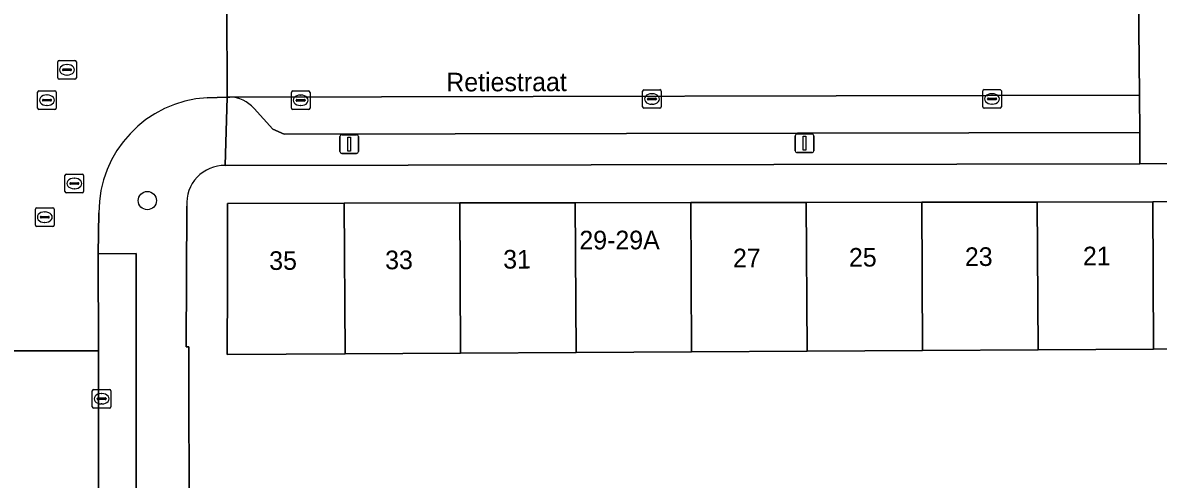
# Model space of a CAD drawing. Extents: x 160732 to 162107, y 387428 to 388479.
# Drawn here: x 161157.5 to 161218.5, y 387935.7 to 387960.1 of the extents above; entities that cross this region are included whole.
import ezdxf

# ---------------------------------------------------------------- set-up
doc = ezdxf.new("R2010")
doc.units = 0
for name, color, linetype in [('IMGEO_Boom', 7, 'Continuous'), ('IMGEO_Erf', 7, 'Continuous'), ('IMGEO_Kolk', 7, 'Continuous'), ('IMGEO_Lichtmast', 7, 'Continuous'), ('IMGEO_Openbare_ruimte_label', 7, 'Continuous'), ('IMGEO_Pand', 7, 'Continuous'), ('IMGEO_Pand_nummerreeks', 7, 'Continuous'), ('IMGEO_Parkeervlak_open', 7, 'Continuous'), ('IMGEO_Rijbaan_lokaal_open', 7, 'Continuous'), ('IMGEO_Rioolput', 7, 'Continuous'), ('IMGEO_Voetpad_open', 7, 'Continuous')]:
    doc.layers.add(name, color=color, linetype=linetype)

msp = doc.modelspace()

# ---------------------------------------------------------------- linework, layer by layer
at = {"layer": 'IMGEO_Boom'}
msp.add_circle((161164.237, 387950.611), 0.489, dxfattribs=at)
at = {"layer": 'IMGEO_Erf'}
for points in [[(161243.083, 387952.638), (161217.507, 387952.589), (161168.418, 387952.495)], [(161166.352, 387950.318), (161166.323, 387942.76), (161166.474, 387942.759), (161166.481, 387932.401)], [(161224.443, 387942.674), (161218.243, 387942.639), (161212.044, 387942.605), (161205.845, 387942.57), (161199.646, 387942.535), (161193.447, 387942.501), (161187.247, 387942.466), (161181.048, 387942.431), (161174.849, 387942.396), (161168.521, 387942.361), (161168.535, 387946.227), (161168.535, 387950.459), (161174.808, 387950.47), (161181.005, 387950.481), (161187.204, 387950.491), (161193.403, 387950.502), (161199.602, 387950.513), (161205.801, 387950.523), (161212, 387950.534), (161218.199, 387950.545), (161224.399, 387950.555)]]:
    msp.add_lwpolyline(points, dxfattribs=at)
msp.add_arc((161168.389, 387950.454), 2.041, 89.17868, 183.81844, dxfattribs=at)
at = {"layer": 'IMGEO_Kolk'}
for p, q in [((161171.967, 387955.563), (161171.967, 387956.415)), ((161172.042, 387956.489), (161172.894, 387956.489)), ((161172.968, 387956.415), (161172.968, 387955.563)), ((161190.816, 387955.632), (161190.816, 387956.484)), ((161190.891, 387956.558), (161191.743, 387956.558)), ((161191.304, 387956.338), (161191.329, 387956.338)), ((161191.817, 387956.484), (161191.817, 387955.632)), ((161209.072, 387955.635), (161209.072, 387956.487)), ((161209.147, 387956.561), (161209.999, 387956.561)), ((161209.56, 387956.341), (161209.585, 387956.341)), ((161210.073, 387956.487), (161210.073, 387955.635)), ((161172.226, 387955.983), (161172.226, 387955.995)), ((161172.664, 387955.946), (161172.266, 387955.946)), ((161172.269, 387956.032), (161172.667, 387956.032)), ((161172.478, 387955.709), (161172.453, 387955.709)), ((161172.455, 387956.269), (161172.48, 387956.269)), ((161172.71, 387955.995), (161172.71, 387955.983)), ((161191.075, 387956.052), (161191.075, 387956.064)), ((161191.513, 387956.015), (161191.115, 387956.015)), ((161191.118, 387956.101), (161191.516, 387956.101)), ((161191.327, 387955.778), (161191.302, 387955.778)), ((161191.559, 387956.064), (161191.559, 387956.052)), ((161209.331, 387956.055), (161209.331, 387956.067)), ((161209.769, 387956.018), (161209.371, 387956.018)), ((161209.374, 387956.104), (161209.772, 387956.104)), ((161209.583, 387955.781), (161209.558, 387955.781)), ((161209.815, 387956.067), (161209.815, 387956.055)), ((161172.894, 387955.489), (161172.042, 387955.489)), ((161191.743, 387955.558), (161190.891, 387955.558)), ((161209.999, 387955.561), (161209.147, 387955.561)), ((161161.358, 387940.483), (161162.21, 387940.483)), ((161161.283, 387939.557), (161161.283, 387940.409)), ((161161.542, 387939.977), (161161.542, 387939.989)), ((161161.98, 387939.94), (161161.582, 387939.94)), ((161161.585, 387940.026), (161161.983, 387940.026)), ((161161.771, 387940.263), (161161.796, 387940.263)), ((161162.026, 387939.989), (161162.026, 387939.977)), ((161162.284, 387940.409), (161162.284, 387939.557)), ((161162.21, 387939.483), (161161.358, 387939.483)), ((161161.794, 387939.703), (161161.769, 387939.703))]:
    msp.add_line(p, q, dxfattribs=at)
for points in [[(161171.967, 387955.563), (161171.967, 387956.415)], [(161172.042, 387956.489), (161172.894, 387956.489)], [(161172.968, 387956.415), (161172.968, 387955.563)], [(161190.816, 387955.632), (161190.816, 387956.484)], [(161190.891, 387956.558), (161191.743, 387956.558)], [(161191.817, 387956.484), (161191.817, 387955.632)], [(161209.072, 387955.635), (161209.072, 387956.487)], [(161209.147, 387956.561), (161209.999, 387956.561)], [(161210.073, 387956.487), (161210.073, 387955.635)], [(161172.894, 387955.489), (161172.042, 387955.489)], [(161191.743, 387955.558), (161190.891, 387955.558)], [(161209.999, 387955.561), (161209.147, 387955.561)], [(161161.358, 387940.483), (161162.21, 387940.483)], [(161161.283, 387939.557), (161161.283, 387940.409)], [(161162.284, 387940.409), (161162.284, 387939.557)], [(161162.21, 387939.483), (161161.358, 387939.483)]]:
    msp.add_lwpolyline(points, dxfattribs=at)
for centre, radius, start, end in [((161172.044, 387956.413), 0.0765, 91.55205, 178.44795), ((161172.044, 387956.413), 0.0765, 91.55205, 178.44795), ((161172.892, 387956.413), 0.0765, 1.55205, 88.44795), ((161172.892, 387956.413), 0.0765, 1.55205, 88.44795), ((161190.893, 387956.482), 0.0765, 91.55205, 178.44795), ((161190.893, 387956.482), 0.0765, 91.55205, 178.44795), ((161191.741, 387956.482), 0.0765, 1.55205, 88.44795), ((161191.741, 387956.482), 0.0765, 1.55205, 88.44795), ((161209.149, 387956.485), 0.0765, 91.55205, 178.44795), ((161209.149, 387956.485), 0.0765, 91.55205, 178.44795), ((161209.997, 387956.485), 0.0765, 1.55205, 88.44795), ((161209.997, 387956.485), 0.0765, 1.55205, 88.44795), ((161172.266, 387955.992), 0.0403, 85.87752, 175.75265), ((161172.263, 387955.982), 0.0366, 178.93798, 274.71019), ((161172.667, 387955.989), 0.043, 264.86636, 352.45326), ((161172.671, 387955.994), 0.0386, 1.73085, 96.63898), ((161191.115, 387956.061), 0.0403, 85.87752, 175.75265), ((161191.112, 387956.051), 0.0366, 178.93798, 274.71019), ((161191.516, 387956.058), 0.043, 264.86636, 352.45326), ((161191.52, 387956.063), 0.0386, 1.73085, 96.63898), ((161209.371, 387956.064), 0.0403, 85.87752, 175.75265), ((161209.368, 387956.054), 0.0366, 178.93798, 274.71019), ((161209.772, 387956.061), 0.043, 264.86636, 352.45326), ((161209.776, 387956.066), 0.0386, 1.73085, 96.63898), ((161172.044, 387955.565), 0.0765, 181.55205, 268.44795), ((161172.044, 387955.565), 0.0765, 181.55205, 268.44795), ((161172.892, 387955.565), 0.0765, 271.55205, 358.44795), ((161172.892, 387955.565), 0.0765, 271.55205, 358.44795), ((161190.893, 387955.634), 0.0765, 181.55205, 268.44795), ((161190.893, 387955.634), 0.0765, 181.55205, 268.44795), ((161191.741, 387955.634), 0.0765, 271.55205, 358.44795), ((161191.741, 387955.634), 0.0765, 271.55205, 358.44795), ((161209.149, 387955.637), 0.0765, 181.55205, 268.44795), ((161209.149, 387955.637), 0.0765, 181.55205, 268.44795), ((161209.997, 387955.637), 0.0765, 271.55205, 358.44795), ((161209.997, 387955.637), 0.0765, 271.55205, 358.44795), ((161161.36, 387940.407), 0.0765, 91.55205, 178.44795), ((161161.36, 387940.407), 0.0765, 91.55205, 178.44795), ((161162.208, 387940.407), 0.0765, 1.55205, 88.44795), ((161162.208, 387940.407), 0.0765, 1.55205, 88.44795), ((161161.582, 387939.986), 0.0403, 85.87752, 175.75265), ((161161.579, 387939.976), 0.0366, 178.93798, 274.71019), ((161161.983, 387939.983), 0.043, 264.86636, 352.45326), ((161161.987, 387939.988), 0.0386, 1.73085, 96.63898), ((161161.36, 387939.559), 0.0765, 181.55205, 268.44795), ((161161.36, 387939.559), 0.0765, 181.55205, 268.44795), ((161162.208, 387939.559), 0.0765, 271.55205, 358.44795), ((161162.208, 387939.559), 0.0765, 271.55205, 358.44795)]:
    msp.add_arc(centre, radius, start, end, dxfattribs=at)
for centre, major_axis, ratio, start_param, end_param in [((161191.303, 387956.058), (-0.387, 0.002), 0.722429, 4.712389, 7.853982), ((161191.328, 387956.058), (-0.39, 0.002), 0.717154, 1.570796, 4.712389), ((161209.559, 387956.061), (-0.387, 0.002), 0.722429, 4.712389, 7.853982), ((161209.584, 387956.061), (-0.39, 0.002), 0.717154, 1.570796, 4.712389), ((161172.454, 387955.989), (-0.387, 0.002), 0.722429, 4.712389, 7.853982), ((161172.479, 387955.989), (-0.39, 0.002), 0.717154, 1.570796, 4.712389), ((161161.77, 387939.983), (-0.387, 0.002), 0.722429, 4.712389, 7.853982), ((161161.795, 387939.983), (-0.39, 0.002), 0.717154, 1.570796, 4.712389)]:
    msp.add_ellipse(centre, major_axis=major_axis, ratio=ratio, start_param=start_param, end_param=end_param, dxfattribs=at)
at = {"layer": 'IMGEO_Lichtmast'}
for p, q in [((161174.573, 387953.242), (161174.573, 387954.042)), ((161174.573, 387954.042), (161174.573, 387953.242)), ((161174.673, 387954.142), (161175.463, 387954.142)), ((161175.463, 387954.142), (161174.673, 387954.142)), ((161175.563, 387954.042), (161175.563, 387953.242)), ((161175.563, 387953.242), (161175.563, 387954.042)), ((161199.013, 387953.282), (161199.013, 387954.082)), ((161199.013, 387954.082), (161199.013, 387953.282)), ((161199.113, 387954.182), (161199.903, 387954.182)), ((161199.903, 387954.182), (161199.113, 387954.182)), ((161200.003, 387954.082), (161200.003, 387953.282)), ((161200.003, 387953.282), (161200.003, 387954.082)), ((161175.463, 387953.142), (161174.673, 387953.142)), ((161174.673, 387953.142), (161175.463, 387953.142)), ((161199.903, 387953.182), (161199.113, 387953.182)), ((161199.113, 387953.182), (161199.903, 387953.182))]:
    msp.add_line(p, q, dxfattribs=at)
for points in [[(161174.993, 387954.017), (161175.143, 387954.017), (161175.143, 387953.267), (161174.993, 387953.267), (161174.993, 387954.017)], [(161199.433, 387954.057), (161199.583, 387954.057), (161199.583, 387953.307), (161199.433, 387953.307), (161199.433, 387954.057)]]:
    msp.add_lwpolyline(points, dxfattribs=at)
for centre, start, end in [((161174.673, 387954.042), 90, 180), ((161174.673, 387954.042), 90, 180), ((161175.463, 387954.042), 0, 90), ((161175.463, 387954.042), 360, 90), ((161199.113, 387954.082), 90, 180), ((161199.113, 387954.082), 90, 180), ((161199.903, 387954.082), 0, 90), ((161199.903, 387954.082), 360, 90), ((161199.113, 387953.282), 180, 270), ((161199.113, 387953.282), 180, 270), ((161199.903, 387953.282), 270, 0), ((161199.903, 387953.282), 270, 0), ((161174.673, 387953.242), 180, 270), ((161174.673, 387953.242), 180, 270), ((161175.463, 387953.242), 270, 0), ((161175.463, 387953.242), 270, 0)]:
    msp.add_arc(centre, 0.1, start, end, dxfattribs=at)
at = {"layer": 'IMGEO_Pand'}
for points in [[(161168.535, 387950.459), (161168.535, 387946.227), (161168.521, 387942.361), (161174.849, 387942.396), (161174.808, 387950.47)], [(161174.808, 387950.47), (161174.849, 387942.396), (161181.048, 387942.431), (161181.005, 387950.481)], [(161181.005, 387950.481), (161181.048, 387942.431), (161187.247, 387942.466), (161187.204, 387950.491)], [(161193.403, 387950.502), (161187.204, 387950.491), (161187.247, 387942.466), (161193.447, 387942.501)], [(161193.403, 387950.502), (161193.447, 387942.501), (161199.646, 387942.535), (161199.602, 387950.513)], [(161199.602, 387950.513), (161199.646, 387942.535), (161205.845, 387942.57), (161205.801, 387950.523)], [(161205.801, 387950.523), (161205.845, 387942.57), (161212.044, 387942.605), (161212, 387950.534)], [(161212, 387950.534), (161212.044, 387942.605), (161218.243, 387942.639), (161218.199, 387950.545)], [(161218.199, 387950.545), (161218.243, 387942.639), (161224.443, 387942.674), (161224.399, 387950.555)]]:
    msp.add_lwpolyline(points, close=True, dxfattribs=at)
at = {"layer": 'IMGEO_Parkeervlak_open'}
for points in [[(161169.968, 387955.554), (161170.974, 387954.445), (161171.575, 387954.168), (161217.496, 387954.255), (161217.48, 387956.261), (161168.663, 387956.165)], [(161163.64, 387917.113), (161163.631, 387947.771), (161161.599, 387947.756), (161161.618, 387942.56), (161161.627, 387913.997)]]:
    msp.add_lwpolyline(points, dxfattribs=at)
msp.add_arc((161168.595, 387954.321), 1.845, 41.92361, 87.89847, dxfattribs=at)
at = {"layer": 'IMGEO_Rijbaan_lokaal_open'}
msp.add_lwpolyline([(161173.705, 387961.122), (161168.507, 387961.118), (161168.516, 387956.165), (161168.663, 387956.165), (161217.48, 387956.261), (161217.376, 387967.03), (161212.367, 387967.026), (161212.393, 387961.222)], close=True, dxfattribs=at)
for points in [[(161167.441, 387956.125), (161168.516, 387956.165), (161168.507, 387961.118), (161166.739, 387961.141)], [(161156.678, 387943.627), (161156.704, 387942.547), (161161.618, 387942.56), (161161.599, 387947.756), (161161.64, 387949.955)], [(161161.627, 387913.926), (161161.627, 387913.997), (161161.618, 387942.56), (161156.704, 387942.547), (161156.776, 387906.254), (161156.817, 387879.896), (161156.803, 387874.965), (161156.836, 387859.504), (161161.733, 387859.513), (161161.702, 387896.422)]]:
    msp.add_lwpolyline(points, dxfattribs=at)
msp.add_arc((161167.792, 387949.983), 6.152, 93.2734, 180.2577, dxfattribs=at)
at = {"layer": 'IMGEO_Rioolput'}
for p, q in [((161159.427, 387957.198), (161159.427, 387958.05)), ((161159.502, 387958.124), (161160.354, 387958.124)), ((161159.686, 387957.618), (161159.686, 387957.63)), ((161160.124, 387957.581), (161159.726, 387957.581)), ((161159.729, 387957.667), (161160.127, 387957.667)), ((161159.915, 387957.904), (161159.94, 387957.904)), ((161160.17, 387957.63), (161160.17, 387957.618)), ((161160.428, 387958.05), (161160.428, 387957.198)), ((161160.354, 387957.124), (161159.502, 387957.124)), ((161159.938, 387957.344), (161159.913, 387957.344)), ((161158.349, 387955.568), (161158.349, 387956.42)), ((161158.424, 387956.494), (161159.276, 387956.494)), ((161159.35, 387956.42), (161159.35, 387955.568)), ((161158.608, 387955.988), (161158.608, 387956)), ((161159.046, 387955.951), (161158.648, 387955.951)), ((161158.651, 387956.037), (161159.049, 387956.037)), ((161158.86, 387955.714), (161158.835, 387955.714)), ((161158.837, 387956.274), (161158.862, 387956.274)), ((161159.092, 387956), (161159.092, 387955.988)), ((161159.276, 387955.494), (161158.424, 387955.494)), ((161159.817, 387951.101), (161159.817, 387951.953)), ((161159.892, 387952.027), (161160.744, 387952.027)), ((161160.076, 387951.521), (161160.076, 387951.533)), ((161160.514, 387951.484), (161160.116, 387951.484)), ((161160.119, 387951.57), (161160.517, 387951.57)), ((161160.305, 387951.807), (161160.33, 387951.807)), ((161160.56, 387951.533), (161160.56, 387951.521)), ((161160.818, 387951.953), (161160.818, 387951.101)), ((161160.744, 387951.027), (161159.892, 387951.027)), ((161160.328, 387951.247), (161160.303, 387951.247)), ((161158.31, 387950.221), (161159.162, 387950.221)), ((161158.235, 387949.295), (161158.235, 387950.147)), ((161158.494, 387949.715), (161158.494, 387949.727)), ((161158.932, 387949.678), (161158.534, 387949.678)), ((161158.537, 387949.764), (161158.935, 387949.764)), ((161158.723, 387950.001), (161158.748, 387950.001)), ((161158.978, 387949.727), (161158.978, 387949.715)), ((161159.236, 387950.147), (161159.236, 387949.295)), ((161159.162, 387949.221), (161158.31, 387949.221)), ((161158.746, 387949.441), (161158.721, 387949.441))]:
    msp.add_line(p, q, dxfattribs=at)
for points in [[(161159.427, 387957.198), (161159.427, 387958.05)], [(161159.502, 387958.124), (161160.354, 387958.124)], [(161160.428, 387958.05), (161160.428, 387957.198)], [(161160.354, 387957.124), (161159.502, 387957.124)], [(161158.349, 387955.568), (161158.349, 387956.42)], [(161158.424, 387956.494), (161159.276, 387956.494)], [(161159.35, 387956.42), (161159.35, 387955.568)], [(161159.276, 387955.494), (161158.424, 387955.494)], [(161159.817, 387951.101), (161159.817, 387951.953)], [(161159.892, 387952.027), (161160.744, 387952.027)], [(161160.818, 387951.953), (161160.818, 387951.101)], [(161160.744, 387951.027), (161159.892, 387951.027)], [(161158.31, 387950.221), (161159.162, 387950.221)], [(161158.235, 387949.295), (161158.235, 387950.147)], [(161159.236, 387950.147), (161159.236, 387949.295)], [(161159.162, 387949.221), (161158.31, 387949.221)]]:
    msp.add_lwpolyline(points, dxfattribs=at)
for centre, radius, start, end in [((161159.504, 387958.048), 0.0765, 91.55205, 178.44795), ((161159.504, 387958.048), 0.0765, 91.55205, 178.44795), ((161159.726, 387957.627), 0.0403, 85.87752, 175.75265), ((161159.723, 387957.617), 0.0366, 178.93798, 274.71019), ((161160.127, 387957.624), 0.043, 264.86636, 352.45326), ((161160.131, 387957.629), 0.0386, 1.73085, 96.63898), ((161160.352, 387958.048), 0.0765, 1.55205, 88.44795), ((161160.352, 387958.048), 0.0765, 1.55205, 88.44795), ((161159.504, 387957.2), 0.0765, 181.55205, 268.44795), ((161159.504, 387957.2), 0.0765, 181.55205, 268.44795), ((161160.352, 387957.2), 0.0765, 271.55205, 358.44795), ((161160.352, 387957.2), 0.0765, 271.55205, 358.44795), ((161158.426, 387956.418), 0.0765, 91.55205, 178.44795), ((161158.426, 387956.418), 0.0765, 91.55205, 178.44795), ((161159.274, 387956.418), 0.0765, 1.55205, 88.44795), ((161159.274, 387956.418), 0.0765, 1.55205, 88.44795), ((161158.648, 387955.997), 0.0403, 85.87752, 175.75265), ((161158.645, 387955.987), 0.0366, 178.93798, 274.71019), ((161159.049, 387955.994), 0.043, 264.86636, 352.45326), ((161159.053, 387955.999), 0.0386, 1.73085, 96.63898), ((161158.426, 387955.57), 0.0765, 181.55205, 268.44795), ((161158.426, 387955.57), 0.0765, 181.55205, 268.44795), ((161159.274, 387955.57), 0.0765, 271.55205, 358.44795), ((161159.274, 387955.57), 0.0765, 271.55205, 358.44795), ((161159.894, 387951.951), 0.0765, 91.55205, 178.44795), ((161159.894, 387951.951), 0.0765, 91.55205, 178.44795), ((161160.116, 387951.53), 0.0403, 85.87752, 175.75265), ((161160.113, 387951.52), 0.0366, 178.93798, 274.71019), ((161160.517, 387951.527), 0.043, 264.86636, 352.45326), ((161160.521, 387951.532), 0.0386, 1.73085, 96.63898), ((161160.742, 387951.951), 0.0765, 1.55205, 88.44795), ((161160.742, 387951.951), 0.0765, 1.55205, 88.44795), ((161159.894, 387951.103), 0.0765, 181.55205, 268.44795), ((161159.894, 387951.103), 0.0765, 181.55205, 268.44795), ((161160.742, 387951.103), 0.0765, 271.55205, 358.44795), ((161160.742, 387951.103), 0.0765, 271.55205, 358.44795), ((161158.312, 387950.145), 0.0765, 91.55205, 178.44795), ((161158.312, 387950.145), 0.0765, 91.55205, 178.44795), ((161159.16, 387950.145), 0.0765, 1.55205, 88.44795), ((161159.16, 387950.145), 0.0765, 1.55205, 88.44795), ((161158.534, 387949.724), 0.0403, 85.87752, 175.75265), ((161158.531, 387949.714), 0.0366, 178.93798, 274.71019), ((161158.935, 387949.721), 0.043, 264.86636, 352.45326), ((161158.939, 387949.726), 0.0386, 1.73085, 96.63898), ((161158.312, 387949.297), 0.0765, 181.55205, 268.44795), ((161158.312, 387949.297), 0.0765, 181.55205, 268.44795), ((161159.16, 387949.297), 0.0765, 271.55205, 358.44795), ((161159.16, 387949.297), 0.0765, 271.55205, 358.44795)]:
    msp.add_arc(centre, radius, start, end, dxfattribs=at)
for centre, major_axis, ratio, start_param, end_param in [((161159.914, 387957.624), (-0.387, 0.002), 0.722429, 4.712389, 7.853982), ((161159.939, 387957.624), (-0.39, 0.002), 0.717154, 1.570796, 4.712389), ((161158.836, 387955.994), (-0.387, 0.002), 0.722429, 4.712389, 7.853982), ((161158.861, 387955.994), (-0.39, 0.002), 0.717154, 1.570796, 4.712389), ((161160.304, 387951.527), (-0.387, 0.002), 0.722429, 4.712389, 7.853982), ((161160.329, 387951.527), (-0.39, 0.002), 0.717154, 1.570796, 4.712389), ((161158.722, 387949.721), (-0.387, 0.002), 0.722429, 4.712389, 7.853982), ((161158.747, 387949.721), (-0.39, 0.002), 0.717154, 1.570796, 4.712389)]:
    msp.add_ellipse(centre, major_axis=major_axis, ratio=ratio, start_param=start_param, end_param=end_param, dxfattribs=at)
at = {"layer": 'IMGEO_Voetpad_open'}
for points in [[(161220.883, 388007.94), (161217.385, 388007.635), (161217.501, 387972.088), (161217.515, 387971.998), (161217.376, 387967.03), (161217.48, 387956.261), (161217.496, 387954.255), (161217.507, 387952.589), (161243.083, 387952.638), (161248.135, 387952.571), (161248.071, 387986.562), (161248.067, 387986.627), (161248.197, 387991.584)], [(161168.418, 387952.495), (161168.516, 387956.165), (161167.441, 387956.125)], [(161168.663, 387956.165), (161168.516, 387956.165), (161168.418, 387952.495), (161217.507, 387952.589), (161217.496, 387954.255)], [(161217.496, 387954.255), (161171.575, 387954.168), (161170.974, 387954.445), (161169.968, 387955.554)], [(161166.474, 387942.759), (161166.323, 387942.76), (161166.352, 387950.318)], [(161161.64, 387949.955), (161161.599, 387947.756), (161163.631, 387947.771), (161163.64, 387917.113)], [(161163.383, 387909.61), (161166.372, 387913.524), (161166.475, 387931.026), (161166.481, 387932.401), (161166.474, 387942.759)]]:
    msp.add_lwpolyline(points, dxfattribs=at)
for centre, radius, start, end in [((161167.792, 387949.983), 6.152, 93.2734, 180.2577), ((161168.595, 387954.321), 1.845, 41.92361, 87.89847), ((161168.389, 387950.454), 2.041, 89.17868, 183.81844)]:
    msp.add_arc(centre, radius, start, end, dxfattribs=at)

# ---------------------------------------------------------------- texts
at = {"layer": 'IMGEO_Openbare_ruimte_label'}
msp.add_text('Retiestraat', height=1, rotation=0.17189, dxfattribs=at).set_placement((161180.282, 387956.462))
at = {"layer": 'IMGEO_Pand_nummerreeks'}
for s, rotation, p in [('29-29A', 0.10313, (161187.425, 387947.991)), ('35', 0.32074, (161170.781, 387946.89)), ('33', 0.32074, (161177.004, 387946.925)), ('31', 0.32074, (161183.339, 387946.961)), ('27', 0.32074, (161195.671, 387947.03)), ('25', 0.32074, (161201.894, 387947.065)), ('23', 0.32074, (161208.116, 387947.099)), ('21', 0.32074, (161214.451, 387947.135))]:
    msp.add_text(s, height=1, rotation=rotation, dxfattribs=at).set_placement(p)

doc.saveas('drawing.dxf')
